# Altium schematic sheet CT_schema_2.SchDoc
size 356 x 211 mm
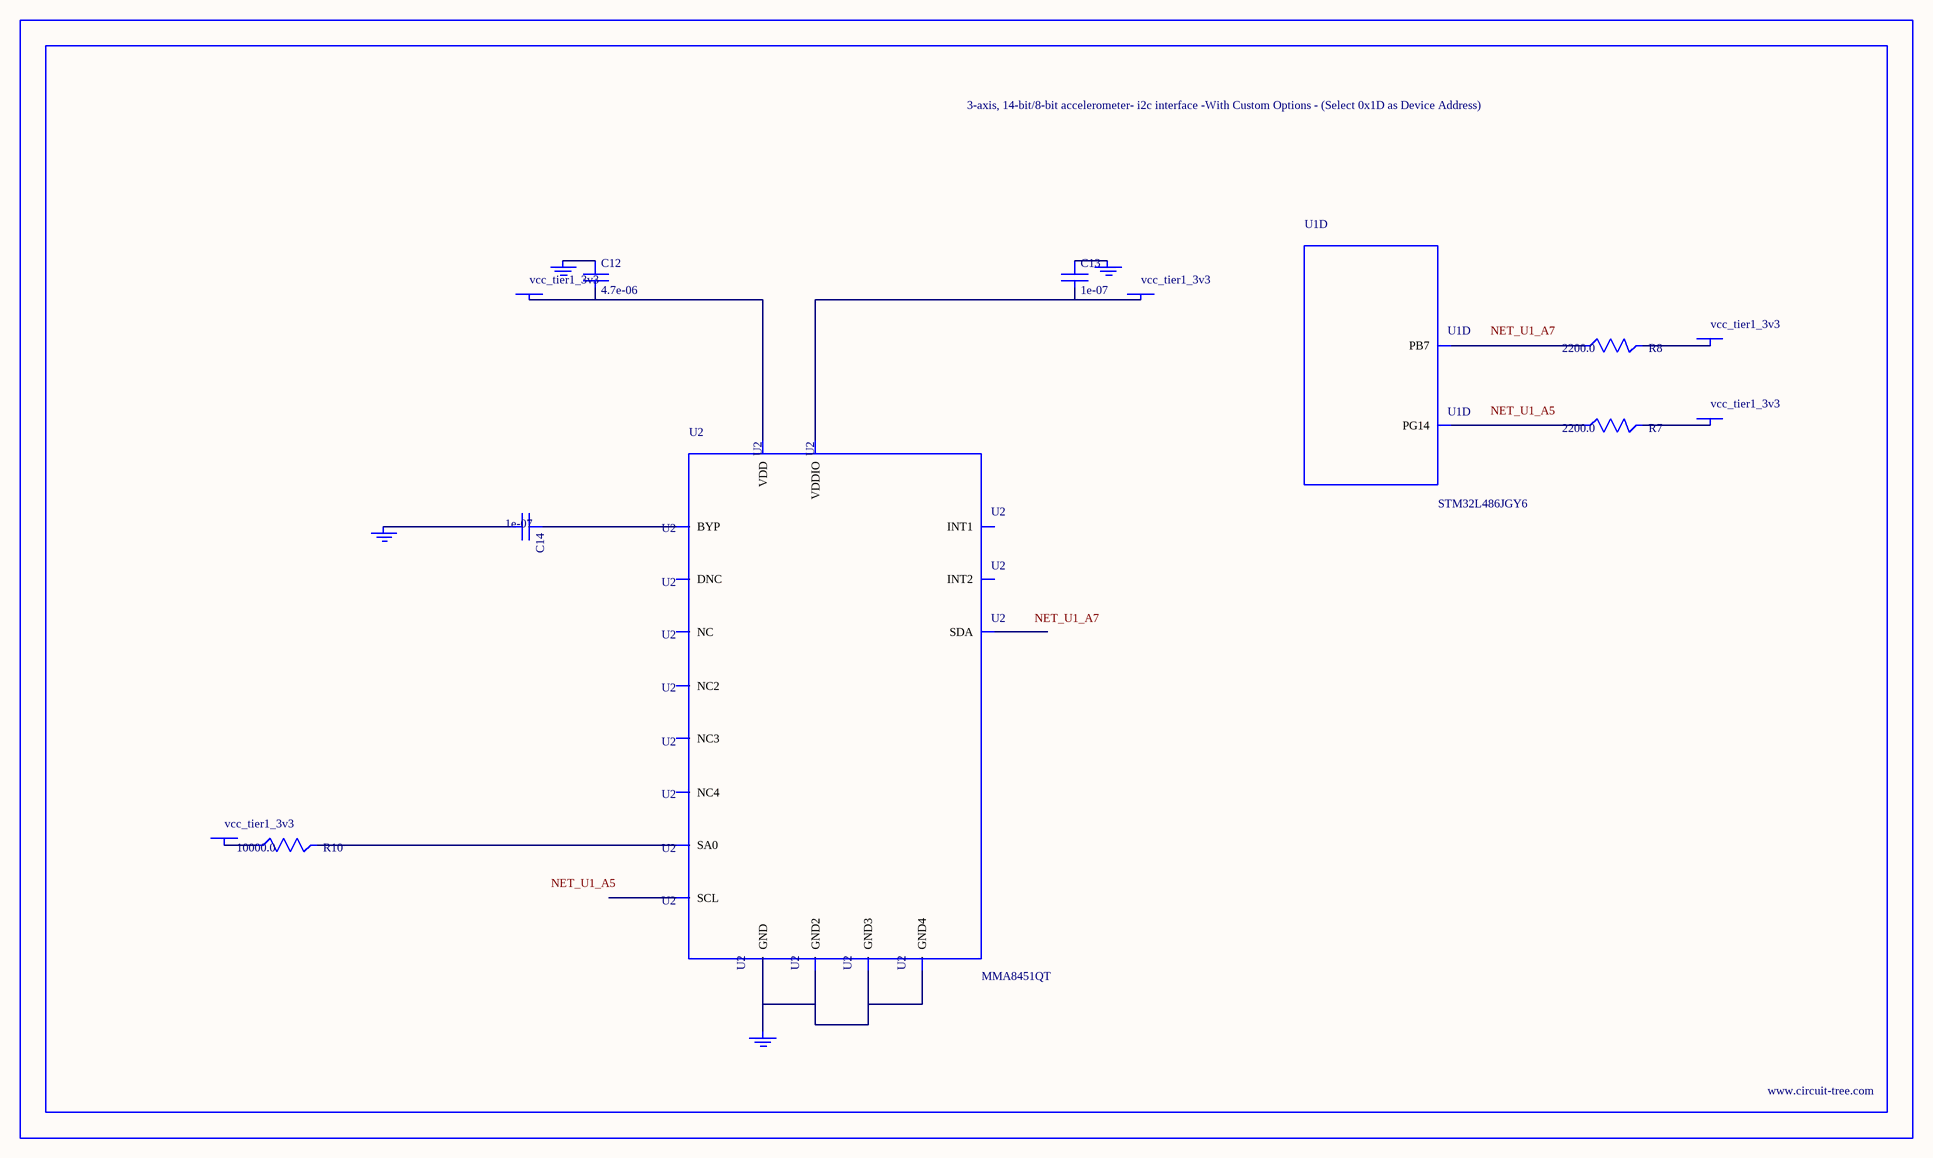
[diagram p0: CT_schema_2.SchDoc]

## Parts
BORDER1  (no value)
C12  4.7e-06  [C0805]
C13  1e-07  [C0402]
C14  1e-07  [C0402]
GND_INSTANCE_1_0  (no value)
GND_INSTANCE_1_1  (no value)
GND_INSTANCE_1_2  (no value)
GND_INSTANCE_1_3  (no value)
POWER_INSTANCE_1_0  vcc_tier1_3v3
POWER_INSTANCE_1_1  vcc_tier1_3v3
POWER_INSTANCE_1_2  vcc_tier1_3v3
POWER_INSTANCE_1_3  vcc_tier1_3v3
POWER_INSTANCE_1_4  vcc_tier1_3v3
R7  2200.0  [R0603]
R8  2200.0  [R0603]
R10  10000.0  [R0603]
U1  STM32L486JGY6  [WLCSP72]  (part D of 7)
U2  MMA8451QT  [QFN-16]

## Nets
NetC12_1: C12.1 GND_INSTANCE_1_2.0(GND)
NetC12_2: C12.2 POWER_INSTANCE_1_2.0(PWR) U2.14(VDD)
NetC13_1: C13.1 GND_INSTANCE_1_0.0(GND)
NetC13_2: C13.2 POWER_INSTANCE_1_0.0(PWR) U2.1(VDDIO)
NetC14_1: C14.1 U2.2(BYP)
NetC14_2: C14.2 GND_INSTANCE_1_1.0(GND)
NetGND_INSTANCE_1_3_0: GND_INSTANCE_1_3.0(GND) U2.5(GND) U2.10(GND2) U2.12(GND3) U2.17(GND4)
NetPOWER_INSTANCE_1_1_0: POWER_INSTANCE_1_1.0(PWR) R10.1
NetPOWER_INSTANCE_1_3_0: POWER_INSTANCE_1_3.0(PWR) R8.2
NetPOWER_INSTANCE_1_4_0: POWER_INSTANCE_1_4.0(PWR) R7.2
NetR7_1: R7.1 U1.A5(PG14)
NetR8_1: R8.1 U1.A7(PB7)
NetR10_2: R10.2 U2.7(SA0)

Not connected (* = marked no-connect by the designer): U2 3(DNC) 4(SCL) 6(SDA) 8(NC) 9(INT2) 11(INT1) 13(NC2) 15(NC3) 16(NC4)

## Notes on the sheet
- Labels drawn without touching a wire or pin: NET_U1_A5, NET_U1_A7

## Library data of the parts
BORDER1 = BORDER_PAGE1
C12 = C0805C475K4RACTU
C13 C14 = C0402C104K3RACTU
GND_INSTANCE_1_0-GND_INSTANCE_1_3 = GND
POWER_INSTANCE_1_0-POWER_INSTANCE_1_4 = PWR
R7 R8 = RC0603JR-072K2L
R10 = RC0603JR-0710KL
